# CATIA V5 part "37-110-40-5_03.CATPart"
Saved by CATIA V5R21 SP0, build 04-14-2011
Part number: 37-110-40-5_03
Bounding box of the stored display mesh (mm): x -5 to 20, y 0 to 10.499, z -20 to 20
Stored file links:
  C:\Users\zerma\Pictures\Stage Stomate\37-110-40-5_03.CATPart
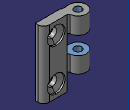
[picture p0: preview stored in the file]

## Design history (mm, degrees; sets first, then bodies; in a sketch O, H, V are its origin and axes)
AxisSystem1: origin (0, 0, 0), X (1, 0, 0), Y (0, 1, 0), Z (0, 0, 1)
Body1 "37-110-40-5_03" (main body)
  Solid1: solid without history
  Sketch1 on face of Solid1, origin (0, 0, 0), H (1, 0, 0), V (0, 1, 0)
    line L1 (-14, 30) -> (6, 30)
    line L2 (6, 30) -> (6, 0)
    line L3 (6, 0) -> (-14, 0)
    line L4 (-14, 0) -> (-14, 30)
    reference projected line E1 (6, 0) -> (6, 5) from edge [face of Solid1 | face of Solid1]
    length L1 = 20
    horizontal: L1 H, L3 H
    vertical: L2 V, L4 V
    coincidence: L2 E1
  Pocket1: profile Sketch1, direction (0, 0, -1), length 0.5
  Sketch2 on face of Solid1, origin (0, 0, -10), H (1, 0, 0), V (0, -1, 0)
    circle A1 centre (0, -5.5) radius 2.25
    reference projected arc E1 centre (0, -5.5) radius 2 from (2, -5.5) to (-2, -5.5) ccw from edge [face of Solid1 | face of Solid1]
    radius A1 = 2.25
    concentricity: A1 E1
  Pocket2: profile Sketch2, direction (0, 0, 1), up to face of Solid1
